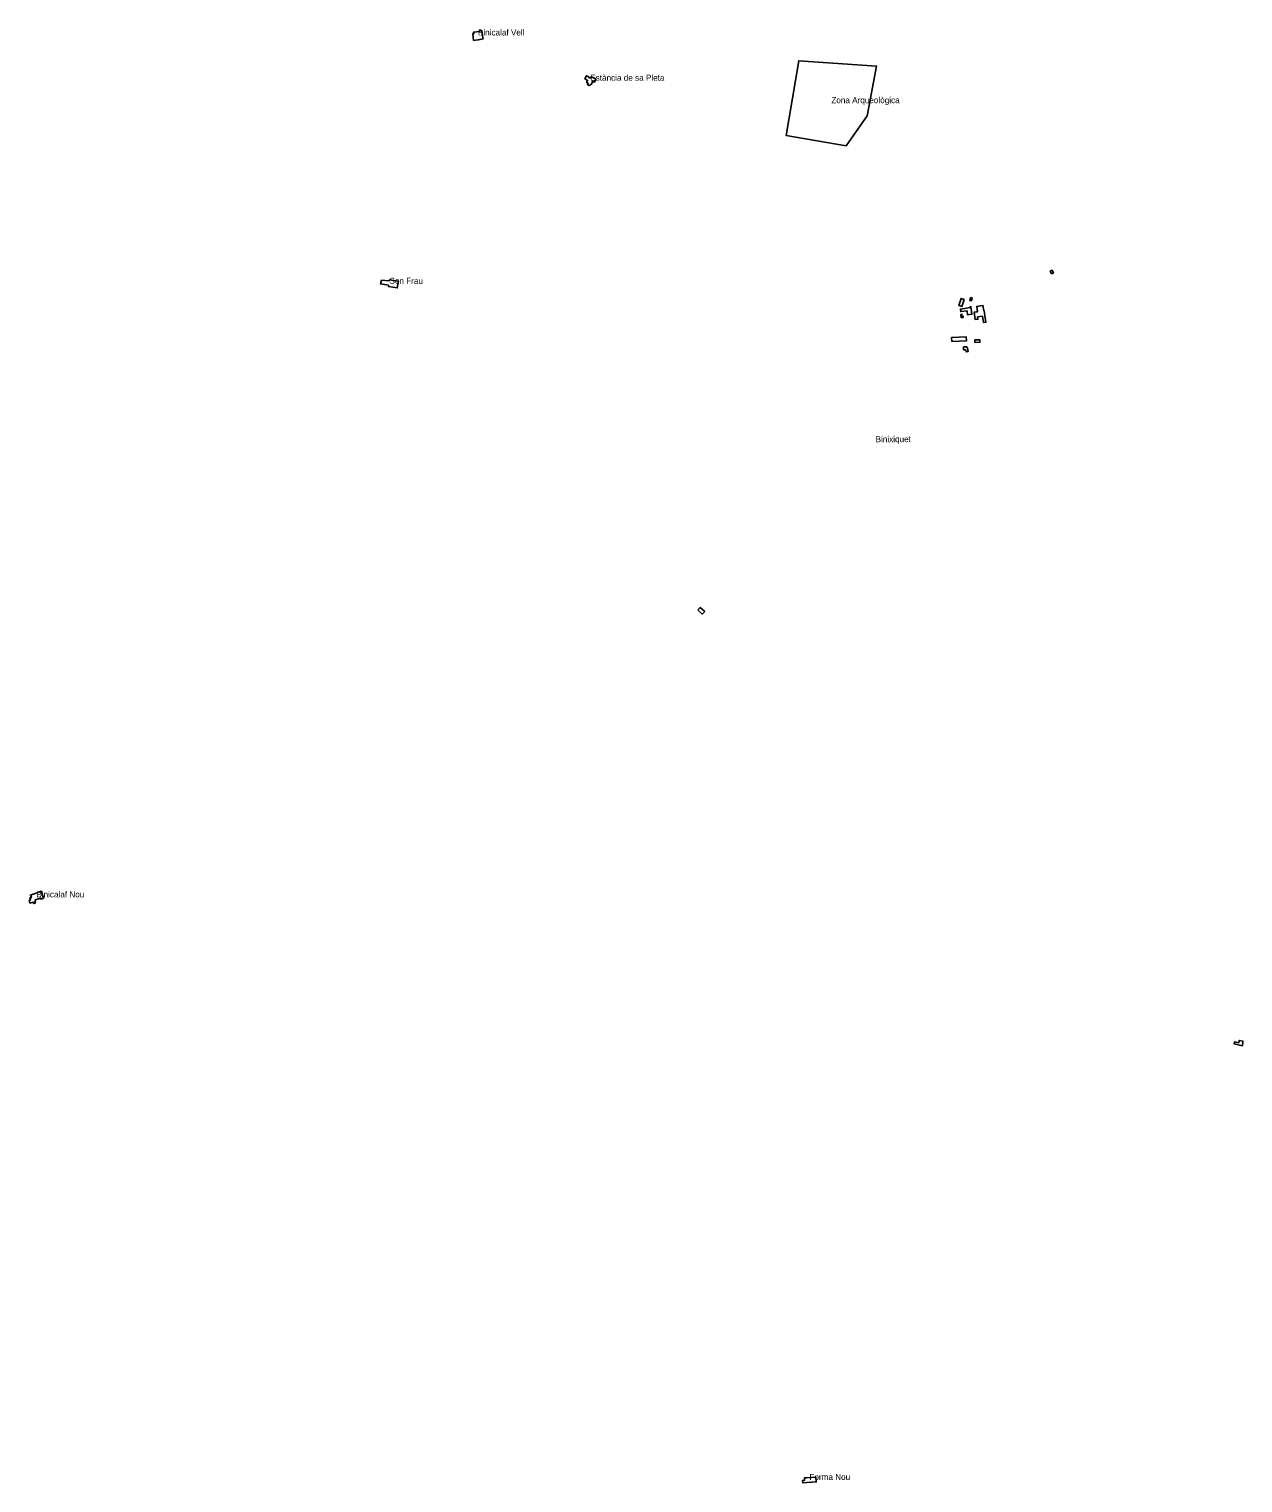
# Model space of a CAD drawing. Extents: x 599451 to 612034, y 4411179 to 4428219.
# Drawn here: x 599451 to 601846, y 4411550 to 4414419 of the extents above; entities that cross this region are included whole.
import ezdxf

# ---------------------------------------------------------------- set-up
doc = ezdxf.new("R2010")
doc.units = 0
doc.layers.add('Bé Arquitectònic', color=7, linetype='Continuous')
doc.layers.add('Muralla_ Perímetre de Protecció', color=7, linetype='Continuous')

msp = doc.modelspace()

# ---------------------------------------------------------------- linework, layer by layer
at = {"layer": 'Bé Arquitectònic'}
for points in [[(600328.1, 4414410.1), (600326.4, 4414409.9), (600327.9, 4414397.2), (600331.9, 4414397.5), (600337.1, 4414398), (600340.5, 4414398.7), (600344, 4414399.5), (600346.6, 4414400.1), (600346.1, 4414403.1), (600345, 4414412), (600344.5, 4414416.5), (600340.3, 4414416), (600340.4, 4414415.2), (600339.9, 4414415.2), (600339.9, 4414414.7), (600327.7, 4414413.3)], [(600554.8, 4414324), (600555.4, 4414325.2), (600550.6, 4414327.2), (600547.4, 4414321.3), (600552.2, 4414318.7), (600553, 4414318.2), (600551, 4414314.4), (600554.1, 4414312.7), (600552.9, 4414310.6), (600552.4, 4414309.6), (600555.9, 4414307.8), (600560.4, 4414310.5), (600562.7, 4414316.1), (600566.2, 4414314.6), (600569, 4414321.3), (600559.7, 4414325.2), (600558.5, 4414322.4)], [(601468.3, 4413936.3), (601471.9, 4413938), (601469.4, 4413943.4), (601465.8, 4413941.7)], [(600146.1, 4413924.1), (600144.1, 4413916.6), (600160, 4413913.8), (600160, 4413911.4), (600177.4, 4413908.6), (600179.8, 4413921.8), (600162.3, 4413924.5), (600161.1, 4413922.5)], [(601290, 4413872.3), (601291.4, 4413871.9), (601295.7, 4413885.6), (601289.8, 4413887.7), (601285.5, 4413873.7)], [(601300.7, 4413868.8), (601288.5, 4413866.7), (601289.1, 4413861.7), (601301.5, 4413863.3), (601302.5, 4413855.3), (601311.2, 4413856.5), (601309.2, 4413871.5), (601307.2, 4413871.2), (601307.4, 4413869.7)], [(601310.4, 4413883.1), (601311.6, 4413888.8), (601308.4, 4413889.4), (601307.2, 4413883.7)], [(601320.8, 4413861.6), (601315.7, 4413860.9), (601317.9, 4413846), (601323, 4413846.8), (601322.3, 4413851.4), (601331.9, 4413852.9), (601333.8, 4413840.5), (601338.9, 4413840.8), (601337, 4413853.6), (601335.5, 4413863.8), (601334.5, 4413863.6), (601332.9, 4413874), (601320.6, 4413872.2), (601322.1, 4413861.8)], [(601289.4, 4413856.4), (601290.1, 4413849.8), (601294.1, 4413850.2), (601293.8, 4413852.7), (601292.1, 4413852.5), (601291.6, 4413856.8)], [(601271.4, 4413802.7), (601300.2, 4413803.9), (601299.9, 4413811.9), (601271.1, 4413810.7)], [(601294.7, 4413786.4), (601298.4, 4413786.5), (601300.7, 4413782.4), (601304.1, 4413783.2), (601302.3, 4413789.8), (601301.1, 4413792.1), (601294.7, 4413792)], [(601317, 4413800.8), (601327, 4413801.2), (601326.8, 4413806.3), (601316.9, 4413805.9)], [(600770.5, 4413273.3), (600779.1, 4413264.8), (600783.9, 4413269.8), (600775.3, 4413278.1)], [(599458.6, 4412711.9), (599453.6, 4412710.2), (599455.4, 4412705.2), (599452.3, 4412704.1), (599453.6, 4412700.3), (599450.8, 4412699.3), (599452.6, 4412694.3), (599458.9, 4412696.5), (599460, 4412693.5), (599463.4, 4412694.8), (599462.4, 4412697.8), (599463.8, 4412698.3), (599463, 4412700.5), (599473.7, 4412704.3), (599474.4, 4412702), (599479.6, 4412703.9), (599474.7, 4412717.7), (599469.8, 4412715.9)], [(601844.7, 4412412.6), (601844.8, 4412413.8), (601845.6, 4412420), (601845.9, 4412422.1), (601838.6, 4412423.4), (601837.9, 4412418.7), (601829.7, 4412420.8), (601828.6, 4412416.7)], [(600984.8, 4411560), (600980.8, 4411559.7), (600980.8, 4411559.2), (600981.1, 4411555.2), (600977.2, 4411554.9), (600977.6, 4411549.9), (600985.5, 4411550.5), (600995, 4411551.3), (601004, 4411552), (601003.2, 4411561), (601003.2, 4411561.5), (600994.2, 4411560.8)]]:
    msp.add_lwpolyline(points, close=True, dxfattribs=at)
at = {"layer": 'Muralla_ Perímetre de Protecció'}
msp.add_lwpolyline([(601063.1, 4414189.3), (601104.6, 4414248.2), (601123, 4414346.5), (600969.6, 4414357.1), (600944.8, 4414209.1)], close=True, dxfattribs=at)

# ---------------------------------------------------------------- texts
at = {"layer": 'Bé Arquitectònic'}
for s, p in [('Binicalaf Vell', (600336.5, 4414406.8)), ('Estància de sa Pleta', (600558.2, 4414317.5)), ('Son Frau', (600161.9, 4413916.6)), ('Binixiquet', (601121.2, 4413604.1)), ('Binicalaf Nou', (599465.2, 4412705.6)), ('Forma Nou', (600990.6, 4411555.7))]:
    msp.add_text(s, height=12, dxfattribs=at).set_placement(p)
at = {"layer": 'Muralla_ Perímetre de Protecció'}
msp.add_text('Zona Arqueològica', height=12, dxfattribs=at).set_placement((601033.9, 4414273.2))

doc.saveas('drawing.dxf')
